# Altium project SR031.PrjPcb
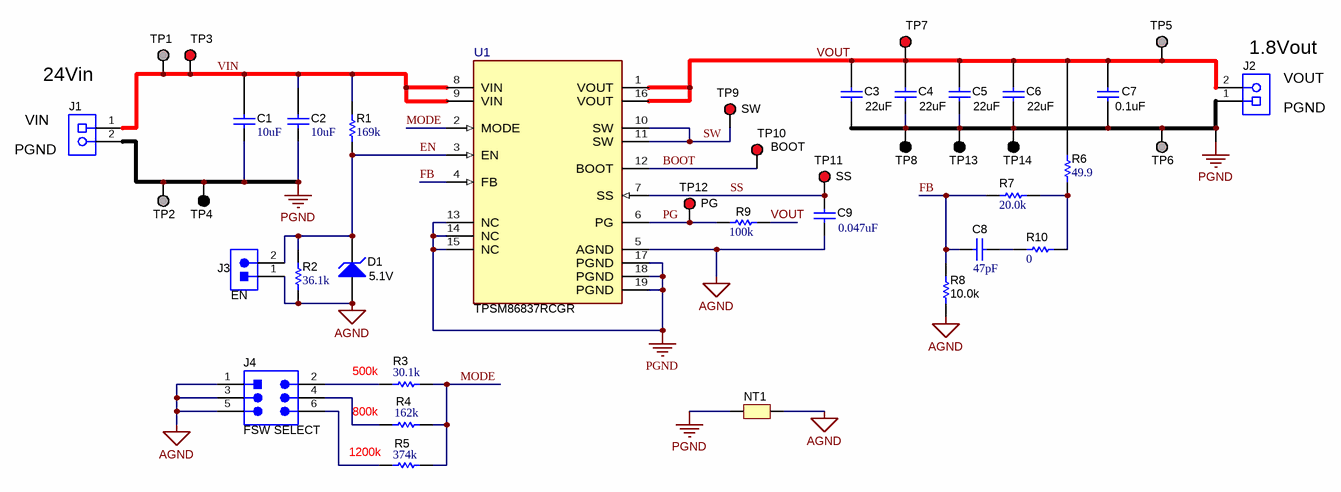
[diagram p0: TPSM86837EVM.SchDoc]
CopyrightYear: 2022; PCB_Layout: Lishuang Zhao; PCB_Rev: A; PRJ_Customer: Public Release; PRJ_Engineer: Lishuang Zhao; PRJ_Number: SR031; PRJ_Title: TPSM86838EVM; SCH_Rev: A; TechSupport: http://www.ti.com/support; TID: N/A
2 sheets, 72 parts. Net scope: global (net labels, ports and power ports of the same name join across sheets).
Board file: TPSM86837EVM.PcbDoc
Sheets:
  TPSM86837EVM.SchDoc
  TPSM86837EVM_Hardware.SchDoc

## Sheet TPSM86837EVM.SchDoc: TPSM86838 schematic
size 431 x 279 mm; REV: A; Date: Not shown in title block; ApprovedBy: Not shown in title block; CheckedBy: Not shown in title block; Author: Not shown in title block; CompanyName: Not shown in title block; DrawnBy: Lishuang Zhao; Engineer: Not shown in title block; Organization: Not shown in title block; Address1: Not shown in title block; Address2: Not shown in title block; Address3: Not shown in title block; Address4: Not shown in title block; DocumentNumber: 1; Revision: Use project parameter SCH_Rev; SheetNumber: 2; SheetTotal: 2; PageSetup: Record=PageOptions¦CenterHorizontal=True¦CenterVertical=True¦PrintScale=1.00¦XCorrection=1.00¦YCorrection=1.00¦PrintKind=0¦BorderSize=5000000¦LeftOffset=0¦BottomOffset=0¦Orientation=2¦PaperLength=1000¦PaperWidth=1000¦Scale=100¦PaperSource=15¦PrintQuality=600¦MediaType=1¦DitherType=10¦PaperKind=Letter¦PrintScaleMode=1

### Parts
C1  ValueDisplayed: 10uF  [1210_270L]  (hidden comment: GRM32ER7YA106KA12L)
C2  ValueDisplayed: 10uF  [1210_270L]  (hidden comment: GRM32ER7YA106KA12L)
C3  ValueDisplayed: 22uF  [1210_270]  (hidden comment: GRM32ER71E226KE15L)
C4  ValueDisplayed: 22uF  [1210_270]  (hidden comment: GRM32ER71E226KE15L)
C5  ValueDisplayed: 22uF  [1210_270]  (hidden comment: GRM32ER71E226KE15L)
C6  ValueDisplayed: 22uF  [1210_270]  (hidden comment: GRM32ER71E226KE15L)
C7  ValueDisplayed: 0.1uF  [0603L]  (hidden comment: CGA3E2X7R1E104K080AA)
C8  ValueDisplayed: 47pF  [0402]  (hidden comment: GRM1555C1H470FA01D)
C9  ValueDisplayed: 0.047uF  [0402]  (hidden comment: C1005X7R1H473K050BB)
D1  value 5.1V  [SOD-323]  (hidden comment: MMSZ5231BS-7-F)
J1  ED120/2DS  [On-Shore_ED120_2DS]  (value not drawn)
J2  ED120/2DS  [On-Shore_ED120_2DS]  (value not drawn)
J3  EN  [TSW-102-07-X-S]
J4  FSW SELECT  [SULLINS_PEC03DAAN]
NT1  Net-Tie  [Net-Tie_10milWide_30milLong]  (value not drawn)  (net tie, no BOM)
R1  ValueDisplayed: 169k  [0402]  (hidden comment: CRCW0402169KFKED)
R2  ValueDisplayed: 36.1k  [0402]  (hidden comment: TNPW040236K1BEED)
R3  ValueDisplayed: 30.1k  [0402]  (hidden comment: RC0402FR-0730K1L)
R4  ValueDisplayed: 162k  [0402]  (hidden comment: CRCW0402162KFKED)
R5  ValueDisplayed: 374k  [0402]  (hidden comment: CRCW0402374KFKED)
R6  ValueDisplayed: 49.9  [0402]  (hidden comment: RC0402FR-0749R9L)
R7  ValueDisplayed: 20.0k  [0402]  (hidden comment: CRCW040220K0FKED)
R8  ValueDisplayed: 10.0k  [0402]  (hidden comment: CRCW040210K0FKED)
R9  ValueDisplayed: 100k  [0402]  (hidden comment: RC1005F104CS)
R10  ValueDisplayed: 0  [0402]  (hidden comment: CRCW04020000Z0ED)
TP1  VIN  [Keystone1502-2]  (value not drawn)
TP2  PGND  [Keystone1502-2]  (value not drawn)
TP3  VIN S+  [Keystone5010]  (value not drawn)
TP4  VIN S-  [Keystone5011]  (value not drawn)
TP5  Vout  [Keystone1502-2]  (value not drawn)
TP6  PGND  [Keystone1502-2]  (value not drawn)
TP7  VOUT S+  [Keystone5010]  (value not drawn)
TP8  VOUT S-  [Keystone5011]  (value not drawn)
TP9  SW  [Keystone5010]
TP10  BOOT  [Keystone5010]
TP11  SS  [Keystone5010]
TP12  PG  [Keystone5010]
TP13  PGND  [Keystone5011]  (value not drawn)
TP14  PGND  [Keystone5011]  (value not drawn)
U1  TPSM86837RCGR  [RCG0019A-MFG]

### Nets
AGND: C9.2 D1.2(A) J3.1 J4.1 J4.3 J4.5 NT1.1 R2.1 R8.1 U1.5(AGND)
PGND: C1.1 C2.1 C3.2 C4.2 C5.2 C6.2 C7.2 J1.2 J2.1 NT1.2 TP2.1 TP4.1 TP6.1 TP8.1 TP13.1 TP14.1 U1.13(NC) U1.14(NC) U1.15(NC) U1.17(PGND) U1.18(PGND) U1.19(PGND)
BOOT: TP10.1 U1.12(BOOT)
EN: D1.1(K) J3.2 R1.1 R2.2 U1.3(EN)
FB: C8.2 R7.1 R8.2 U1.4(FB)
MODE: R3.2 R4.2 R5.2 U1.2(MODE)
PG: R9.1 TP12.1 U1.6(PG)
SS: C9.1 TP11.1 U1.7(SS)
SW: TP9.1 U1.10(SW) U1.11(SW)
VIN: C1.2 C2.2 J1.1 R1.2 TP1.1 TP3.1 U1.8(VIN) U1.9(VIN)
VOUT: C3.1 C4.1 C5.1 C6.1 C7.1 J2.2 R6.2 R9.2 TP5.1 TP7.1 U1.1(VOUT) U1.16(VOUT)
NetC8_1: C8.1 R10.1
NetJ4_2: J4.2 R3.1
NetJ4_4: J4.4 R4.1
NetJ4_6: J4.6 R5.1
NetR6_1: R6.1 R7.2 R10.2

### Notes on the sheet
- (near J1) 24Vin
- (near J2) VOUT
- (near J2) 1.8Vout
- (near J1) PGND
- (near J1) VIN
- (near J2) PGND
- (near R3) 500k
- 800k
- 1200k

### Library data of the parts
C1 C2 = CMP-0009233-2: CAP, CERM, 10 uF, 35 V, +/- 10%, X7R, 1210; Manufacturer: MuRata; SizeZ_mm: 2.7; Value: 10uF; Value2: 35V; Cap_Case: 1210; Cap_F: 10µF; Value1: Unknown; TaMin_C: -55°C; U/M: EA; SizeArea_mm2: 8; TaMax_C: 125°C; AEC Category: Q200; SizeX_mm: 3.2; SizeY_mm: 2.5; Polarized: N; SizeAreaWB_mm2: 14.7
C3-C6 = CMP-0009224-2: CAP, CERM, 22 uF, 25 V, +/- 10%, X7R, 1210; Manufacturer: MuRata; TaMin_C: -55°C; Polarized: N; SizeAreaWB_mm2: 14.7; Value1: Unknown; U/M: EA; Value: 22uF; TaMax_C: 125°C; SizeZ_mm: 2.7; SizeX_mm: 3.2; SizeY_mm: 2.5; Cap_Case: 1210; Value2: 25V; SizeArea_mm2: 8; CompType: Capacitor; Cap_F: 22µF; AEC Category: Q200
C7 = CMP-0007077-5: CAP, CERM, 0.1 uF, 25 V, +/- 10%, X7R, AEC-Q200 Grade 1, 0603; Manufacturer: TDK; TaMin_C: -55°C; Polarized: N; SizeAreaWB_mm2: 4.68; Value1: Unknown; U/M: EA; Value: 0.1uF; TaMax_C: 125°C; SizeZ_mm: 1; SizeX_mm: 1.6; SizeY_mm: 0.8; Cap_Case: 0603; Value2: 25V; SizeArea_mm2: 1.28; AEC Qualified: Y; Cap_F: 100nF; AEC Category: Q200
C8 = CMP-0006467-2: CAP, CERM, 47 pF, 50 V, +/- 1%, C0G/NP0, 0402; Manufacturer: MuRata; TaMin_C: -55°C; Polarized: N; SizeAreaWB_mm2: 3; Value1: Unknown; U/M: EA; Value: 47pF; TaMax_C: 125°C; SizeZ_mm: 0.6; SizeX_mm: 1; SizeY_mm: 0.5; Value2: 50V; AEC Category: Q200
C9 = CMP-0006298-2: CAP, CERM, 0.047 uF, 50 V, +/- 10%, X7R, 0402; Manufacturer: TDK; TaMin_C: -55°C; ESR_ohm: 64.07m; Polarized: N; SizeAreaWB_mm2: 3; Value1: 0.06407 ohm; U/M: EA; SizeZ_mm: 0.6; SizeX_mm: 1; SizeY_mm: 0.5; Value2: 50V; Cap_F: 47nF; IRMS_A: 646.122mA; AEC Category: Q200; TaMax_C: 125°C
D1 = CMP-0005854-3: Diode, Zener, 5.1 V, 200 mW, SOD-323; Manufacturer: Diodes Inc.; SizeX_mm: 2.7; SizeZ_mm: 1; RJA_CperW: 350; Power_W: 200mW; SizeAreaWB_mm2: 8.695; AEC Category: Q101; Value1: 0.2W; SizeArea_mm2: 3.645; SizeY_mm: 1.35
J1 J2 = CMP-0074910-1: Terminal Block, 5.08 mm, 2x1, Brass, TH; Manufacturer: On-Shore Technology; Cert_VDE: Y; CNHeader: False; Current_A: 15A; Green_Lifecycle: Not Set; Shrouded: N; Gender: Female; Green_REACh: Incomplete; Voltage_V: 300V; Row_Count: 1; Pitch_mm: 5.08; CT: True
J3 = CMP-0075405-1: Header, 100mil, 2x1, Gold, TH; PartNumber: TSW-102-07-G-S; Manufacturer: Samtec; Pitch_mm: 2.54; Cert_VDE: N; Gender: Male; Cert_CSA: Y; Voltage_V: 550V; Green_REACh: Passed; Current_A: 6.3A; CT: False; Green_Lifecycle: Active; Row_Count: 1; CNHeader: True
J4 = CMP-0054552-2: Header, 100mil, 3x2, Tin, TH; Manufacturer: Sullins Connector Solutions; PartNumber: PEC03DAAN; Current_A: 3A; Green_Lifecycle: Not Set; Shrouded: N; Gender: Male; Green_REACh: Incomplete; Voltage_V: 1.8kV; Row_Count: 2; RowSpacing_mm: 2.54; Cert_UL: Y
NT1 = CMP-0078142-4: Single point connection between nets.
R1 = CMP-0026038-1: RES, 169 k, 1%, 0.063 W, 0402; Manufacturer: Vishay-Dale; Power_W: 63mW; TempCo: 100 ppm/C; U/M: EA; Value: 169k; EIA_Code: E96; SizeX_mm: 1; SizeY_mm: 0.5; SizeZ_mm: 0.6; Value2: 0.063W; VDC_V: 50V; AEC Category: Q200
R2 = CMP-0026820-1: RES, 36.1 k, 0.1%, 0.063 W, AEC-Q200 Grade 1, 0402; Manufacturer: Vishay-Dale; Power_W: 63mW; TempCo: 25 ppm/C; Value_Code: 36k1; U/M: EA; Value: 36.1k; EIA_Code: E192; SizeX_mm: 1; SizeY_mm: 0.5; SizeZ_mm: 0.6; Value2: 0.063W; AEC Qualified: Y; VDC_V: 50V; AEC Category: Q200
R3 = CMP-0026730-1: RES, 30.1 k, 1%, 0.063 W, 0402; Manufacturer: Yageo America; Power_W: 63mW; TempCo: 100 ppm/C; Value_Code: 30k1; Value: 30.1k; EIA_Code: E96; SizeX_mm: 1; SizeY_mm: 0.5; SizeZ_mm: 0.6; Value2: 0.063W; AEC Qualified: N; VDC_V: 50V; AEC Category: Q200; U/M: EA
R4 = CMP-0026034-3: RES, 162 k, 1%, 0.063 W, AEC-Q200 Grade 0, 0402; Manufacturer: Vishay-Dale; Power_W: 63mW; TempCo: 100 ppm/C; Value: 162k; EIA_Code: E96; SizeX_mm: 1; SizeY_mm: 0.5; SizeZ_mm: 0.6; Value2: 0.063W; AEC Qualified: Y; VDC_V: 50V; AEC Category: Q200; AEC Grade: 0
R5 = CMP-0026317-2: RES, 374 k, 1%, 0.063 W, AEC-Q200 Grade 0, 0402; Manufacturer: Vishay-Dale; Power_W: 63mW; TempCo: 100 ppm/C; Value: 374k; EIA_Code: E96; SizeX_mm: 1; SizeY_mm: 0.5; SizeZ_mm: 0.6; Value2: 0.063W; AEC Qualified: Y; VDC_V: 50V; AEC Category: Q200; AEC Grade: 0
R6 = CMP-0026738-1: RES, 49.9, 1%, 0.063 W, 0402; Manufacturer: Yageo America; Power_W: 63mW; TempCo: 100 ppm/C; Value_Code: 49R9; U/M: EA; Value: 49.9; EIA_Code: E96; SizeX_mm: 1; SizeY_mm: 0.5; SizeZ_mm: 0.6; Value2: 0.063W; AEC Qualified: N; VDC_V: 50V; AEC Category: Q200
R7 = CMP-0026162-2: RES, 20.0 k, 1%, 0.063 W, AEC-Q200 Grade 0, 0402; Manufacturer: Vishay-Dale; Power_W: 63mW; TempCo: 100 ppm/C; Value_Code: 20k0; Value: 20.0k; EIA_Code: E96; Res_ohm: 20k; SizeX_mm: 1; SizeY_mm: 0.5; SizeZ_mm: 0.6; Value2: 0.063W; AEC Qualified: Y; VDC_V: 50V; AEC Category: Q200; AEC Grade: 0
R8 = CMP-0025958-3: RES, 10.0 k, 1%, 0.063 W, AEC-Q200 Grade 0, 0402; Manufacturer: Vishay-Dale; Power_W: 63mW; TempCo: 100 ppm/C; Value_Code: 10k0; Value: 10.0k; EIA_Code: E96; Res_ohm: 10k; SizeX_mm: 1; SizeY_mm: 0.5; SizeZ_mm: 0.6; Value2: 0.063W; AEC Qualified: Y; VDC_V: 50V; AEC Category: Q200; AEC Grade: 0
R9 = CMP-0026745-1: RES, 100 k, 1%, 0.063 W, 0402; Manufacturer: Samsung Electro-Mechanics; Power_W: 63mW; TempCo: 100 ppm/C; U/M: EA; Value: 100k; EIA_Code: E96; SizeX_mm: 1; SizeY_mm: 0.5; SizeZ_mm: 0.6; Value2: 0.063W; AEC Qualified: N; VDC_V: 80V; AEC Category: Q200
R10 = CMP-0026822-1: RES, 0, 5%, 0.063 W, 0402; Manufacturer: Vishay-Dale; Power_W: 63mW; TempCo: 200 ppm/C; Value_Code: 0000; U/M: EA; Value: 0; EIA_Code: E24; SizeX_mm: 1; SizeY_mm: 0.5; SizeZ_mm: 0.6; Value2: 0.063W; VDC_V: 50V; AEC Category: Q200
TP1 TP2 TP5 TP6 = CMP-0055113-1: Terminal, Turret, TH, Double; PartNumber: 1502-2; Manufacturer: Keystone; CompType: Turret Terminal; CNHeader: FALSE; Green_Lifecycle: Active; Green_REACh: Passed
TP3 TP7 TP9-TP12 = CMP-0055147-1: Test Point, Multipurpose, Red, TH; Manufacturer: Keystone; PartNumber: 5010; CNHeader: FALSE; Green_Lifecycle: Active; Green_REACh: Passed; ContactFinish: Silver; CT: TRUE
TP4 TP8 TP13 TP14 = CMP-0055148-1: Test Point, Multipurpose, Black, TH; Manufacturer: Keystone; PartNumber: 5011; CNHeader: FALSE; Green_Lifecycle: Active; Green_REACh: Passed; ContactFinish: Silver; CT: TRUE
U1 = CMP-0121040-3: 4.5V - 28V, 8A Buck Power Module; Manufacturer: Texas Instruments; SizeZ_mm: 4.1mm; Standoff Height: 0mm; AEC Category: Q200; CompType: IC

## Sheet TPSM86837EVM_Hardware.SchDoc: TPSM86838 schematic
size 431 x 279 mm; Date: Not shown in title block; ApprovedBy: Not shown in title block; CheckedBy: Not shown in title block; Author: Not shown in title block; CompanyName: Not shown in title block; DrawnBy: Lishuang Zhao; Engineer: Not shown in title block; Organization: Not shown in title block; Address1: Not shown in title block; Address2: Not shown in title block; Address3: Not shown in title block; Address4: Not shown in title block; DocumentNumber: 1; Revision: Use project parameter SCH_Rev; SheetNumber: 1; SheetTotal: 2; PageSetup: Record=PageOptions¦CenterHorizontal=True¦CenterVertical=True¦PrintScale=1.00¦XCorrection=1.00¦YCorrection=1.00¦PrintKind=0¦BorderSize=5000000¦LeftOffset=0¦BottomOffset=0¦Orientation=2¦PaperLength=1000¦PaperWidth=1000¦Scale=100¦PaperSource=15¦PrintQuality=600¦MediaType=1¦DitherType=10¦PaperKind=Letter¦PrintScaleMode=1
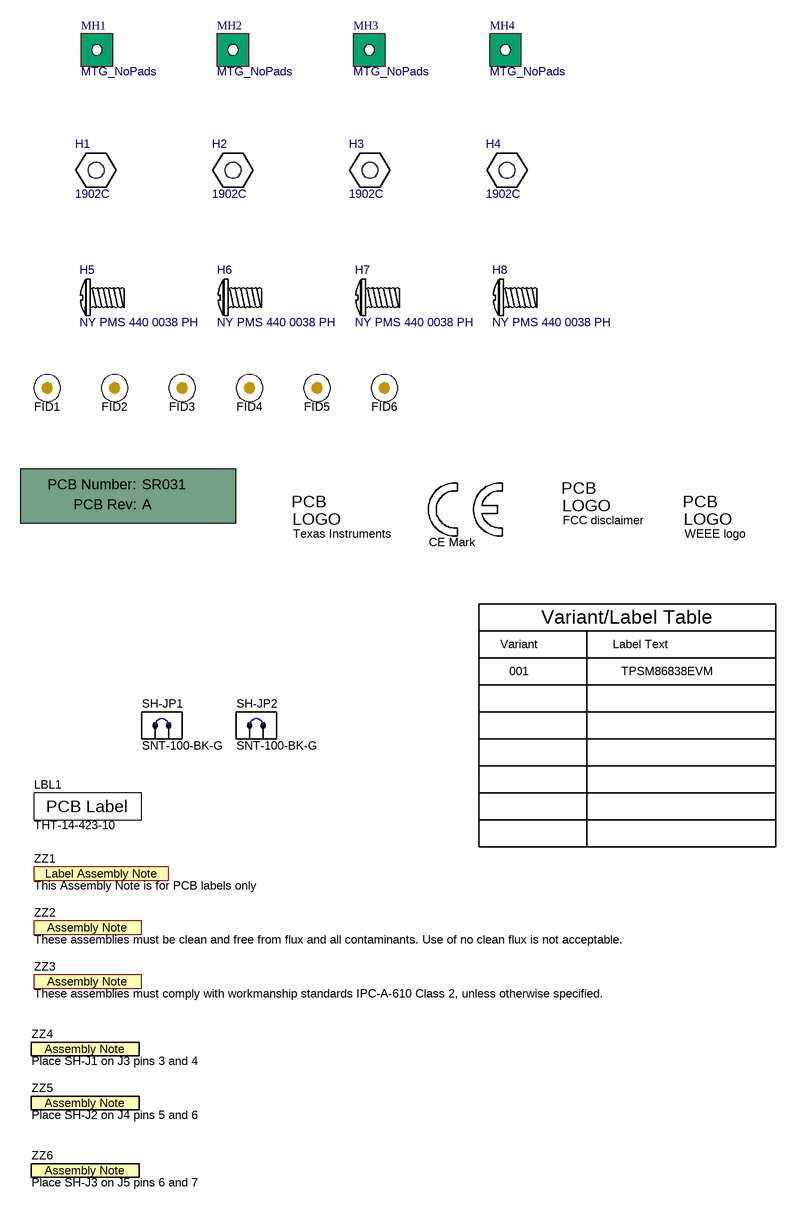
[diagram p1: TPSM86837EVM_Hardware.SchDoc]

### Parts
!PCB1  Printed Circuit Board  (value not drawn)  (mechanical)
FID1  Fiducial  [Fiducial10-20]  (value not drawn)
FID2  Fiducial  [Fiducial10-20]  (value not drawn)
FID3  Fiducial  [Fiducial10-20]  (value not drawn)
FID4  Fiducial  [Fiducial10-20]  (value not drawn)
FID5  Fiducial  [Fiducial10-20]  (value not drawn)
FID6  Fiducial  [Fiducial10-20]  (value not drawn)
H1  1902C  [Keystone_1902C]  (mechanical)
H2  1902C  [Keystone_1902C]  (mechanical)
H3  1902C  [Keystone_1902C]  (mechanical)
H4  1902C  [Keystone_1902C]  (mechanical)
H5  NY PMS 440 0038 PH  (mechanical)
H6  NY PMS 440 0038 PH  (mechanical)
H7  NY PMS 440 0038 PH  (mechanical)
H8  NY PMS 440 0038 PH  (mechanical)
LBL1  THT-14-423-10  [Label_650x200]
Logo1  CE Mark  [CE_Mark_5mm]  (no BOM)
Logo2  Texas Instruments  [TI_Stacked_Overlay_Small]  (no BOM)
Logo4  WEEE logo  [WEEE_Minimum]  (no BOM)
Logo?  FCC disclaimer  [FCC_disclaimer]  (no BOM)
MH1  MTG_NoPads  [MTG_159mil]  (no BOM)
MH2  MTG_NoPads  [MTG_159mil]  (no BOM)
MH3  MTG_NoPads  [MTG_159mil]  (no BOM)
MH4  MTG_NoPads  [MTG_159mil]  (no BOM)
SH-JP1  SNT-100-BK-G  [SNT-100-BK-G]
SH-JP2  SNT-100-BK-G  [SNT-100-BK-G]
ZZ1  This Assembly Note is for PCB labels only  [AssemblyNoteLabel]  (no BOM)
ZZ2  These assemblies must be clean and free from flux and all contaminants. Use of no clean flux is not acceptable.  [AssemblyNote]  (no BOM)
ZZ3  These assemblies must comply with workmanship standards IPC-A-610 Class 2, unless otherwise specified.  [AssemblyNote]  (no BOM)
ZZ4  Place SH-J1 on J3 pins 3 and 4  [AssemblyNote]  (no BOM)
ZZ5  Place SH-J2 on J4 pins 5 and 6  [AssemblyNote]  (no BOM)
ZZ6  Place SH-J3 on J5 pins 6 and 7  [AssemblyNote]  (no BOM)

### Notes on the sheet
- Variant/Label Table
- Variant
- 001
- Label Text
- TPSM86838EVM

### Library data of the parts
!PCB1 = CMP-0003618-2: Manufacturer: Any; PartNumber: SR031
FID1-FID6 = CMP-0077181-1: Fiducial mark.  There is nothing to buy or mount.
H1-H4 = CMP-0003610-1: Standoff, Hex, 0.5"L #4-40 Nylon; Manufacturer: Keystone; CompType: Hardware
H5-H8 = CMP-0003667-1: Screw, Pan Head , 4-40, 3/8", Nylon; Manufacturer: B&F Fastener Supply; CompType: Hardware
LBL1 = CMP-0003625-1: Thermal Transfer Printable Labels, 0.650" W x 0.200" H - 10,000 per roll; Manufacturer: Brady; Note: Size: 0.65" x 0.20 "
Logo1 = CMP-0074844-1: SymbolCreator: a0412235
Logo2 = CMP-0074838-1: Texas Instrument Corporate Signature; SymbolCreator: a0412235; Lib Reference: TI_Logo; Library Reference: Logo
Logo4 = CMP-0074769-1
Logo? = CMP-0074847-1: FCC_disclaimer; Library Reference: Logo
MH1-MH4 = CMP-0078424-2: PCB Mounting Hole, No Pad; Manufacturer: Any; Key: Mounting Hole (non-standard) No Pad
SH-JP1 SH-JP2 = CMP-0003623-3: Shunt, 100mil, Gold plated, Black; Manufacturer: Samtec; Alternate Manufacturer: 3M; Alternate PartNumber: 969102-0000-DA; Value: 1x2; Note: You can "mate" this to a header by matching the designator.  i.e. use SH-J3 for header J3
ZZ1 = CMP-0003616-3
ZZ2 = CMP-0077237-1
ZZ3 = CMP-0077238-1
ZZ4-ZZ6 = CMP-0003615-1: This Assembly Note will show in the PcbDoc and associated outputs

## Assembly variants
001: not fitted C6 R3; alternate parts U1 -> CMP-0034284-1
002: alternate parts U1 -> CMP-0121040-3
